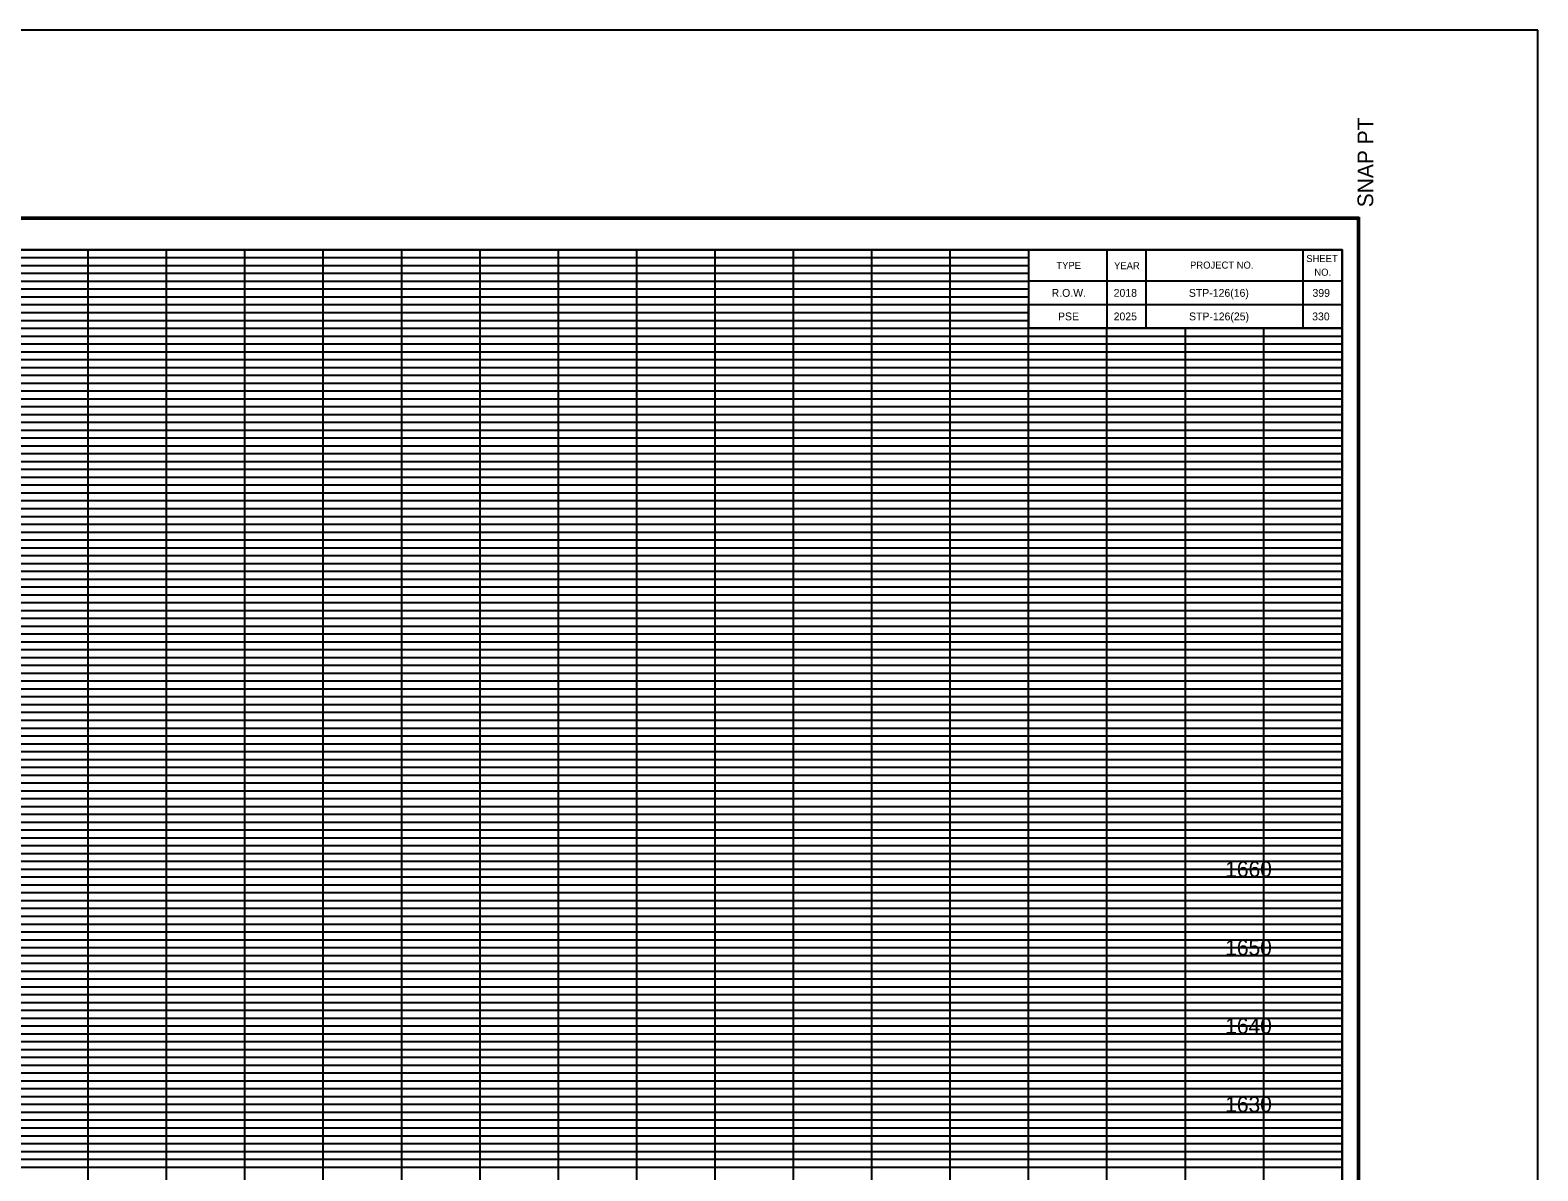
# Model space of a CAD drawing. Extents: x 955 to 1375, y 1248 to 3657.
# Drawn here: x 1152.6 to 1345, y 3252.5 to 3398 of the extents above; entities that cross this region are included whole.
import ezdxf

# ---------------------------------------------------------------- set-up
doc = ezdxf.new("R2010")
doc.units = 0
for name, color, linetype in [('DESIGN - SCRATCH - User 1', 7, 'Continuous'), ('DESIGN - SHEET - Corner Text', 7, 'Continuous'), ('DESIGN - SHEET - Light Grid', 7, 'Continuous'), ('DESIGN - SHEET - Linework', 7, 'Continuous'), ('DESIGN - SHEET - Plot Shape', 7, 'Continuous'), ('DESIGN - TYPICAL - Text', 7, 'Continuous'), ('DESIGN - UTILITIES - Cable (Overhead) with Text', 7, 'Continuous'), ('SURVEY - NON-TRANSPORTATION - Features Text', 7, 'Continuous')]:
    doc.layers.add(name, color=color, linetype=linetype)

# ---------------------------------------------------------------- blocks, each defined once
blk = doc.blocks.new('XSTSHT')
at = {"layer": 'DESIGN - SCRATCH - User 1'}
for p, q in [((28.5, 20.45), (28.5, 20.45)), ((29.24, 20.45), (29.24, 20.45)), ((30.49, 20.45), (30.49, 20.45)), ((31.74, 20.45), (31.74, 20.45)), ((28.5, 20.15), (28.5, 20.15)), ((29.24, 20.15), (29.24, 20.15)), ((30.49, 20.15), (30.49, 20.15)), ((31.74, 20.15), (31.74, 20.15))]:
    blk.add_line(p, q, dxfattribs=at)
at = {"layer": 'DESIGN - SHEET - Light Grid'}
for p, q in [((8, 20.9), (16, 20.9)), ((8, 20.8), (16, 20.8)), ((16, 20.9), (24, 20.9)), ((16, 20.8), (24, 20.8)), ((24, 20.9), (28, 20.9)), ((24, 20.8), (28, 20.8)), ((8, 20.7), (16, 20.7)), ((8, 20.6), (16, 20.6)), ((16, 20.7), (24, 20.7)), ((16, 20.6), (24, 20.6)), ((24, 20.7), (28, 20.7)), ((24, 20.6), (28, 20.6)), ((8, 20.5), (16, 20.5)), ((8, 20.4), (16, 20.4)), ((16, 20.5), (24, 20.5)), ((16, 20.4), (24, 20.4)), ((24, 20.5), (28, 20.5)), ((24, 20.4), (28, 20.4)), ((8, 20.3), (16, 20.3)), ((16, 20.3), (24, 20.3)), ((24, 20.3), (28, 20.3)), ((8, 20.2), (16, 20.2)), ((8, 20.1), (16, 20.1)), ((16, 20.2), (24, 20.2)), ((16, 20.1), (24, 20.1)), ((24, 20.2), (28, 20.2)), ((24, 20.1), (28, 20.1)), ((8, 19.9), (16, 19.9)), ((16, 19.9), (24, 19.9)), ((24, 19.9), (32, 19.9)), ((8, 19.8), (16, 19.8)), ((8, 19.7), (16, 19.7)), ((16, 19.8), (24, 19.8)), ((16, 19.7), (24, 19.7)), ((24, 19.8), (32, 19.8)), ((24, 19.7), (32, 19.7)), ((8, 19.6), (16, 19.6)), ((8, 19.5), (16, 19.5)), ((16, 19.6), (24, 19.6)), ((16, 19.5), (24, 19.5)), ((24, 19.6), (32, 19.6)), ((24, 19.5), (32, 19.5)), ((8, 19.4), (16, 19.4)), ((8, 19.3), (16, 19.3)), ((16, 19.4), (24, 19.4)), ((16, 19.3), (24, 19.3)), ((24, 19.4), (32, 19.4)), ((24, 19.3), (32, 19.3)), ((8, 19.2), (16, 19.2)), ((8, 19.1), (16, 19.1)), ((16, 19.2), (24, 19.2)), ((16, 19.1), (24, 19.1)), ((24, 19.2), (32, 19.2)), ((24, 19.1), (32, 19.1)), ((8, 18.9), (16, 18.9)), ((16, 18.9), (24, 18.9)), ((24, 18.9), (32, 18.9)), ((8, 18.8), (16, 18.8)), ((8, 18.7), (16, 18.7)), ((16, 18.8), (24, 18.8)), ((16, 18.7), (24, 18.7)), ((24, 18.8), (32, 18.8)), ((24, 18.7), (32, 18.7)), ((8, 18.6), (16, 18.6)), ((8, 18.5), (16, 18.5)), ((16, 18.6), (24, 18.6)), ((16, 18.5), (24, 18.5)), ((24, 18.6), (32, 18.6)), ((24, 18.5), (32, 18.5)), ((8, 18.4), (16, 18.4)), ((8, 18.3), (16, 18.3)), ((16, 18.4), (24, 18.4)), ((16, 18.3), (24, 18.3)), ((24, 18.4), (32, 18.4)), ((24, 18.3), (32, 18.3)), ((8, 18.2), (16, 18.2)), ((8, 18.1), (16, 18.1)), ((16, 18.2), (24, 18.2)), ((16, 18.1), (24, 18.1)), ((24, 18.2), (32, 18.2)), ((24, 18.1), (32, 18.1)), ((8, 17.9), (16, 17.9)), ((16, 17.9), (24, 17.9)), ((24, 17.9), (32, 17.9)), ((8, 17.8), (16, 17.8)), ((8, 17.7), (16, 17.7)), ((16, 17.8), (24, 17.8)), ((16, 17.7), (24, 17.7)), ((24, 17.8), (32, 17.8)), ((24, 17.7), (32, 17.7)), ((8, 17.6), (16, 17.6)), ((16, 17.6), (24, 17.6)), ((24, 17.6), (32, 17.6)), ((8, 17.5), (16, 17.5)), ((8, 17.4), (16, 17.4)), ((16, 17.5), (24, 17.5)), ((16, 17.4), (24, 17.4)), ((24, 17.5), (32, 17.5)), ((24, 17.4), (32, 17.4)), ((8, 17.3), (16, 17.3)), ((8, 17.2), (16, 17.2)), ((16, 17.3), (24, 17.3)), ((16, 17.2), (24, 17.2)), ((24, 17.3), (32, 17.3)), ((24, 17.2), (32, 17.2)), ((8, 17.1), (16, 17.1)), ((16, 17.1), (24, 17.1)), ((24, 17.1), (32, 17.1)), ((8, 16.9), (16, 16.9)), ((8, 16.8), (16, 16.8)), ((16, 16.9), (24, 16.9)), ((16, 16.8), (24, 16.8)), ((24, 16.9), (32, 16.9)), ((24, 16.8), (32, 16.8)), ((8, 16.7), (16, 16.7)), ((8, 16.6), (16, 16.6)), ((16, 16.7), (24, 16.7)), ((16, 16.6), (24, 16.6)), ((24, 16.7), (32, 16.7)), ((24, 16.6), (32, 16.6)), ((8, 16.5), (16, 16.5)), ((8, 16.4), (16, 16.4)), ((16, 16.5), (24, 16.5)), ((16, 16.4), (24, 16.4)), ((24, 16.5), (32, 16.5)), ((24, 16.4), (32, 16.4)), ((8, 16.3), (16, 16.3)), ((8, 16.2), (16, 16.2)), ((16, 16.3), (24, 16.3)), ((16, 16.2), (24, 16.2)), ((24, 16.3), (32, 16.3)), ((24, 16.2), (32, 16.2)), ((8, 16.1), (16, 16.1)), ((16, 16.1), (24, 16.1)), ((24, 16.1), (32, 16.1)), ((8, 15.9), (16, 15.9)), ((8, 15.8), (16, 15.8)), ((16, 15.9), (24, 15.9)), ((16, 15.8), (24, 15.8)), ((24, 15.9), (32, 15.9)), ((24, 15.8), (32, 15.8)), ((8, 15.7), (16, 15.7)), ((8, 15.6), (16, 15.6)), ((16, 15.7), (24, 15.7)), ((16, 15.6), (24, 15.6)), ((24, 15.7), (32, 15.7)), ((24, 15.6), (32, 15.6)), ((8, 15.5), (16, 15.5)), ((8, 15.4), (16, 15.4)), ((16, 15.5), (24, 15.5)), ((16, 15.4), (24, 15.4)), ((24, 15.5), (32, 15.5)), ((24, 15.4), (32, 15.4)), ((8, 15.3), (16, 15.3)), ((8, 15.2), (16, 15.2)), ((16, 15.3), (24, 15.3)), ((16, 15.2), (24, 15.2)), ((24, 15.3), (32, 15.3)), ((24, 15.2), (32, 15.2)), ((8, 15.1), (16, 15.1)), ((16, 15.1), (24, 15.1)), ((24, 15.1), (32, 15.1)), ((8, 14.9), (16, 14.9)), ((16, 14.9), (24, 14.9)), ((24, 14.9), (32, 14.9)), ((8, 14.8), (16, 14.8)), ((8, 14.7), (16, 14.7)), ((16, 14.8), (24, 14.8)), ((16, 14.7), (24, 14.7)), ((24, 14.8), (32, 14.8)), ((24, 14.7), (32, 14.7)), ((8, 14.6), (16, 14.6)), ((8, 14.5), (16, 14.5)), ((16, 14.6), (24, 14.6)), ((16, 14.5), (24, 14.5)), ((24, 14.6), (32, 14.6)), ((24, 14.5), (32, 14.5)), ((8, 14.4), (16, 14.4)), ((8, 14.3), (16, 14.3)), ((16, 14.4), (24, 14.4)), ((16, 14.3), (24, 14.3)), ((24, 14.4), (32, 14.4)), ((24, 14.3), (32, 14.3)), ((8, 14.2), (16, 14.2)), ((8, 14.1), (16, 14.1)), ((16, 14.2), (24, 14.2)), ((16, 14.1), (24, 14.1)), ((24, 14.2), (32, 14.2)), ((24, 14.1), (32, 14.1)), ((8, 13.9), (16, 13.9)), ((16, 13.9), (24, 13.9)), ((24, 13.9), (32, 13.9)), ((8, 13.8), (16, 13.8)), ((8, 13.7), (16, 13.7)), ((16, 13.8), (24, 13.8)), ((16, 13.7), (24, 13.7)), ((24, 13.8), (32, 13.8)), ((24, 13.7), (32, 13.7)), ((8, 13.6), (16, 13.6)), ((8, 13.5), (16, 13.5)), ((16, 13.6), (24, 13.6)), ((16, 13.5), (24, 13.5)), ((24, 13.6), (32, 13.6)), ((24, 13.5), (32, 13.5)), ((8, 13.4), (16, 13.4)), ((8, 13.3), (16, 13.3)), ((16, 13.4), (24, 13.4)), ((16, 13.3), (24, 13.3)), ((24, 13.4), (32, 13.4)), ((24, 13.3), (32, 13.3)), ((8, 13.2), (16, 13.2)), ((8, 13.1), (16, 13.1)), ((16, 13.2), (24, 13.2)), ((16, 13.1), (24, 13.1)), ((24, 13.2), (32, 13.2)), ((24, 13.1), (32, 13.1)), ((8, 12.9), (16, 12.9)), ((16, 12.9), (24, 12.9)), ((24, 12.9), (32, 12.9)), ((8, 12.8), (16, 12.8)), ((8, 12.7), (16, 12.7)), ((16, 12.8), (24, 12.8)), ((16, 12.7), (24, 12.7)), ((24, 12.8), (32, 12.8)), ((24, 12.7), (32, 12.7)), ((8, 12.6), (16, 12.6)), ((16, 12.6), (24, 12.6)), ((24, 12.6), (32, 12.6)), ((8, 12.5), (16, 12.5)), ((8, 12.4), (16, 12.4)), ((16, 12.5), (24, 12.5)), ((16, 12.4), (24, 12.4)), ((24, 12.5), (32, 12.5)), ((24, 12.4), (32, 12.4)), ((8, 12.3), (16, 12.3)), ((8, 12.2), (16, 12.2)), ((16, 12.3), (24, 12.3)), ((16, 12.2), (24, 12.2)), ((24, 12.3), (32, 12.3)), ((24, 12.2), (32, 12.2)), ((8, 12.1), (16, 12.1)), ((16, 12.1), (24, 12.1)), ((24, 12.1), (32, 12.1)), ((8, 11.9), (16, 11.9)), ((8, 11.8), (16, 11.8)), ((16, 11.9), (24, 11.9)), ((16, 11.8), (24, 11.8)), ((24, 11.9), (32, 11.9)), ((24, 11.8), (32, 11.8)), ((8, 11.7), (16, 11.7)), ((8, 11.6), (16, 11.6)), ((16, 11.7), (24, 11.7)), ((16, 11.6), (24, 11.6)), ((24, 11.7), (32, 11.7)), ((24, 11.6), (32, 11.6)), ((8, 11.5), (16, 11.5)), ((8, 11.4), (16, 11.4)), ((16, 11.5), (24, 11.5)), ((16, 11.4), (24, 11.4)), ((24, 11.5), (32, 11.5)), ((24, 11.4), (32, 11.4)), ((8, 11.3), (16, 11.3)), ((8, 11.2), (16, 11.2)), ((16, 11.3), (24, 11.3)), ((16, 11.2), (24, 11.2)), ((24, 11.3), (32, 11.3)), ((24, 11.2), (32, 11.2)), ((8, 11.1), (16, 11.1)), ((16, 11.1), (24, 11.1)), ((24, 11.1), (32, 11.1)), ((8, 10.9), (16, 10.9)), ((8, 10.8), (16, 10.8)), ((16, 10.9), (24, 10.9)), ((16, 10.8), (24, 10.8)), ((24, 10.9), (32, 10.9)), ((24, 10.8), (32, 10.8)), ((8, 10.7), (16, 10.7)), ((8, 10.6), (16, 10.6)), ((16, 10.7), (24, 10.7)), ((16, 10.6), (24, 10.6)), ((24, 10.7), (32, 10.7)), ((24, 10.6), (32, 10.6)), ((8, 10.5), (16, 10.5)), ((8, 10.4), (16, 10.4)), ((16, 10.5), (24, 10.5)), ((16, 10.4), (24, 10.4)), ((24, 10.5), (32, 10.5)), ((24, 10.4), (32, 10.4)), ((8, 10.3), (16, 10.3)), ((8, 10.2), (16, 10.2)), ((16, 10.3), (24, 10.3)), ((16, 10.2), (24, 10.2)), ((24, 10.3), (32, 10.3)), ((24, 10.2), (32, 10.2)), ((8, 10.1), (16, 10.1)), ((16, 10.1), (24, 10.1)), ((24, 10.1), (32, 10.1)), ((8, 9.9), (16, 9.9)), ((16, 9.9), (24, 9.9)), ((24, 9.9), (32, 9.9)), ((8, 9.8), (16, 9.8)), ((8, 9.7), (16, 9.7)), ((16, 9.8), (24, 9.8)), ((16, 9.7), (24, 9.7)), ((24, 9.8), (32, 9.8)), ((24, 9.7), (32, 9.7)), ((8, 9.6), (16, 9.6)), ((8, 9.5), (16, 9.5)), ((16, 9.6), (24, 9.6)), ((16, 9.5), (24, 9.5)), ((24, 9.6), (32, 9.6)), ((24, 9.5), (32, 9.5)), ((8, 9.4), (16, 9.4)), ((8, 9.3), (16, 9.3)), ((16, 9.4), (24, 9.4)), ((16, 9.3), (24, 9.3)), ((24, 9.4), (32, 9.4)), ((24, 9.3), (32, 9.3))]:
    blk.add_line(p, q, dxfattribs=at)
at = {"layer": 'DESIGN - SHEET - Linework'}
for p, q in [((-1.823, 21.414), (32.217, 21.414)), ((32.217, 21.414), (32.217, -0.414)), ((16, 0), (16, 21)), ((17, 0), (17, 21)), ((18, 0), (18, 21)), ((19, 0), (19, 21)), ((20, 0), (20, 21)), ((21, 0), (21, 21)), ((22, 0), (22, 21)), ((23, 0), (23, 21)), ((24, 0), (24, 21)), ((25, 0), (25, 21)), ((26, 0), (26, 21)), ((27, 0), (27, 21)), ((0, 20), (28, 20)), ((28, 0), (28, 20)), ((29, 0), (29, 20)), ((30, 0), (30, 20)), ((31, 0), (31, 20)), ((0, 19), (32, 19)), ((0, 18), (32, 18)), ((0, 17), (32, 17)), ((0, 16), (32, 16)), ((0, 15), (32, 15)), ((0, 14), (32, 14)), ((0, 13), (32, 13)), ((0, 12), (32, 12)), ((0, 11), (32, 11)), ((0, 10), (32, 10))]:
    blk.add_line(p, q, dxfattribs=at)
for points in [[(0, 21), (0, 0), (32, 0), (32, 21), (0, 21)], [(28, 21), (28, 20), (32, 20), (32, 21), (31.5, 21), (31.5, 20), (29.5, 20), (29.5, 21), (29, 21), (29, 20), (32, 20), (28, 20), (28, 20.3), (32, 20.3), (32, 20.6), (28, 20.6)]]:
    blk.add_lwpolyline(points, dxfattribs=at)
at = {"layer": 'DESIGN - SHEET - Plot Shape'}
for points in [[(-1.803, 21.394), (32.197, 21.394), (32.197, -0.394), (-1.803, -0.394)], [(-0.85, 21), (32, 21), (32, -0.25), (-0.85, -0.25)]]:
    blk.add_lwpolyline(points, close=True, dxfattribs=at)
at = {"layer": 'DESIGN - SHEET - Corner Text'}
blk.add_text('  SNAP PT', height=0.2, rotation=90, dxfattribs=at).set_placement((32.397, 21.394))
for s, p in [('TYPE', (28.354, 20.756)), ('YEAR', (29.09, 20.752)), ('PROJECT NO.', (30.06, 20.76)), ('SHEET', (31.543, 20.843)), ('NO.', (31.646, 20.669))]:
    blk.add_text(s, height=0.09, dxfattribs=at).set_placement(p)

msp = doc.modelspace()

# ---------------------------------------------------------------- linework, layer by layer
at = {"layer": 'DESIGN - SHEET - Plot Shape'}
msp.add_lwpolyline([(991.5, 3157.5), (1320, 3157.5), (1320, 3370), (991.5, 3370)], close=True, dxfattribs=at)
at = {"layer": 'SURVEY - NON-TRANSPORTATION - Features Text'}
msp.add_lwpolyline([(955.41, 1505.76), (1344.98, 1505.76), (1344.98, 3398.01), (955.41, 3398.01)], close=True, dxfattribs=at)

# ---------------------------------------------------------------- block references
at = {"layer": 'DESIGN - UTILITIES - Cable (Overhead) with Text', "xscale": 10, "yscale": 10}
msp.add_blockref('XSTSHT', (1000, 3160), dxfattribs=at)

# ---------------------------------------------------------------- texts
at = {"layer": 'DESIGN - SHEET - Corner Text'}
for s, p in [('R.O.W.', (1282.94, 3364)), ('2018', (1290.85, 3364)), ('STP-126(16)', (1300.45, 3364)), ('399', (1316.22, 3364)), ('PSE', (1283.75, 3361)), ('2025', (1290.85, 3361)), ('STP-126(25)', (1300.47, 3361)), ('330', (1316.18, 3361))]:
    msp.add_text(s, height=1, dxfattribs=at).set_placement(p)
at = {"layer": 'DESIGN - TYPICAL - Text'}
for s, p in [('     1660     ', (1301.37, 3290)), ('     1650     ', (1301.37, 3280)), ('     1640     ', (1301.37, 3270)), ('     1630     ', (1301.37, 3260))]:
    msp.add_text(s, height=2, dxfattribs=at).set_placement(p)

doc.saveas('drawing.dxf')
